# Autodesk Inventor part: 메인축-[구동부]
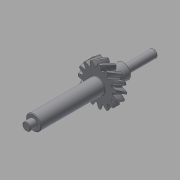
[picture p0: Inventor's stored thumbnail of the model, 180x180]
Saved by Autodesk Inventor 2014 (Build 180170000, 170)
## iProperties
Created: 2016-12
Part Number: 메인축-[구동부]
Material: 강철, 탄소
Document SubType Name: Modeling
Designer: mduedu
Categories: <?xml version="1.0" encoding="UTF-16"?> <MemberInstance><Categories><FamilyTemplate><FamilyTemplateParameter ValueType="xs:double" Id="1" ObjectReferenceKey="da
Density: 7.87 g/cm^3
Appearance: 기본값
Mass: 199.401 g
Surface Area: 86.9137 cm^2
Volume: 25.3368 cm^3
CustomPartVersion: 1
Author: mduedu
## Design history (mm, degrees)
sketch "Sketch1"
  geometry: C1 r 19.321 at (0, 0)
  constraints: 1 centre point
  dimensions: "d0" = 38.64102 diameter of C1 (= da_da)
extrude "Extrusion1" new body sketch "Sketch1" distance "d1" = 10 (= da_b); taper "d2" = 0 deg
workplane "Work Plane2"
sketch "Sketch2"
  geometry: C1 r 19.321 at (0, 0) reference; C2 r 17.321 at (0, 0)
  constraints: 1 centre point, 1 coincident
  dimensions: "d3" = 34.64102 diameter of C2 (= da_dw)
feature "피치 지름" sketch "Sketch2" dims "d4" = 10, "d5" = 0
workplane "Work Plane8"
workplane "Work Plane9"
feature "스퍼 기어" dims "da_b" = 10, "da_d" = 34.64102, "da_aw" = 43.87862, "da_da" = 38.64102, "da_df" = 29.64102, "da_dw" = 34.64102, angle "da_beta" = 30 deg, "da_lefttooth" = 0, "da_righttooth" = 10
sketch "스케치3"
  geometry: C1 r 7.5 at (0, 0); 1 further point
  constraints: 1 centre point, 1 coincident
  dimensions: "d49" = 15 diameter of C1
extrude "돌출2" join sketch "스케치3" distance "d50" = 64; taper "d51" = 0 deg
sketch "스케치4"
  geometry: C1 r 4 at (0, 0); 1 further point
  constraints: 1 centre point, 1 coincident
  dimensions: "d52" = 8 diameter of C1
extrude "돌출3" join sketch "스케치4" distance "d53" = 7; taper "d54" = 0 deg
sketch "스케치5"
  geometry: C1 r 7.5 at (0, 0) reference; 1 further point
extrude "돌출4" join sketch "스케치5" distance "d55" = 16; taper "d56" = 0 deg
sketch "스케치6"
  geometry: C1 r 4 at (0, 0); 1 further point
  constraints: 1 centre point, 1 coincident
  dimensions: "d57" = 8 diameter of C1
extrude "돌출5" join sketch "스케치6" distance "d58" = 30; taper "d59" = 0 deg
chamfer "모따기1" distance "d60" = 0.5; stored, may be unused: second distance "d61" = 2, angle "d62" = 45 deg
fillet "모깎기1" dims "d63" = 0.5
body "Solid1"
body "Srf1"
other parameters: "d16" = 43.87862 (= da_aw), "d17" = 0, "d34" = 12 deg (computed from da_z), "d39" = 0, "d41" = 0, "d43" = 43.87862 (= da_aw), "d46" = 43.87862 (= da_aw), "d47" = 0, "d48" = 0
